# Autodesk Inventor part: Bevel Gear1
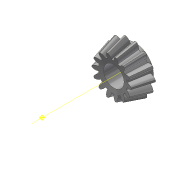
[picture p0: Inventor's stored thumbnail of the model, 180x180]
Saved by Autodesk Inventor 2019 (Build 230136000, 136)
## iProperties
Created: 2019-01
Part Number: Bevel Gear1
Material: Steel, Mild
Document SubType Name: Modeling
Designer: m.vorobev
Categories: <?xml version="1.0" encoding="UTF-16"?> <MemberInstance><Categories><FamilyTemplate><FamilyTemplateParameter ValueType="xs:double" Id="1" ObjectReferenceKey="da
Mass: 60.9118 g
Surface Area: 34.3074 cm^2
Volume: 7.7496 cm^3
Density: 7.86 g/cm^3
Appearance: Steel
CustomPartVersion: 1
Author: m.vorobev
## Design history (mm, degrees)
node "Top Point"
node "Mesh Plane2"
sketch "Teeth Body Sketch"
  geometry: L1 (0, 0)-(23.339, -115.145); L2 (23.339, -115.145)-(31.684, -113.095); L3 (31.684, -113.095)-(0, 0); L4 (28, -114)-(0, 0); L5 (18.368, -90.623)-(24.936, -89.009); L6 (23.339, -115.145)-(18.368, -90.623); L7 (31.684, -113.095)-(24.936, -89.009); L8 (0, -39.387)-(0, 6.564) reference; L9 (0, -114)-(31.684, -114)
  constraints: 16 end point, 4 point on line, 3 perpendicular, 2 collinear, 1 horizontal alignment, 1 vertical alignment
  dimensions: "d0" = 56 diameter of L4.start L8 (= da_de); "d1" = 46.67709 diameter of L1.end L8 (= da_dfe); "d2" = 63.3676 diameter of L2.end L8 (= da_dae); "d3" = 25 distance between parallel lines of L2 L5 (= da_b); "d4" = 113.09521 vertical distance of L2.end L1.start (= da_ve)
revolve "Teeth Body" sketch "Teeth Body Sketch" stored, may be unused: angle "d5" = 90 deg
node "Start Point"
node "Tooth Plane"
sketch "Start Sketch"
  geometry: L1 (0, -23.505)-(0, 10.645) reference; L2 (-1.996, -5.831)-(1.996, -5.831); A1 r 10.858 centre (-12.832, -5.13) between (-1.996, -5.831) and (-9.272, 5.128); A2 r 10.858 centre (12.832, -5.13) between (9.272, 5.128) and (1.996, -5.831); A3 r 35.203 centre (0, -28.832) between (9.272, 5.128) and (-9.272, 5.128); 1 further point
  constraints: 6 point on circle, 3 centre point, 3 symmetric about line, 2 end point, 1 coincident, 1 perpendicular, 1 other
  dimensions: "d7" = 10.85803 radius of A1 (= fd_rr); "d8" = 12.83159 horizontal distance of point (0, -28.832) A1.centre (= fd_x); "d9" = 23.7024 vertical distance of point (0, -28.832) A1.centre (= fd_y); "d57" = 35.20347 radius of A3 (= 0.5 x fd_dva + 0.3 x da_he); "d58" = 23.00101 distance from line of A3.centre L2 (= 0.5 x fd_dva - 1.12 x da_he)
node "End Point"
  node "End Plane"
sketch "3D Sketch Right"
  node "Helical Curve Right" dims "d65" = 419.42516 (computed from da_dm, da_delta, da_beta), "d66" = 31.5, "d67" = 56 (= da_de), "d68" = -2.40846 (= -da_delta), "d69" = 24.69567 (computed from fd_loft, da_delta)
node "End Plane Right"
sketch "End Sketch Right"
  geometry: L1 (0, -33.91)-(0, 15.115) reference; L2 (-1.566, -4.545)-(1.566, -4.545); A1 r 8.517 centre (-10.065, -3.995) between (-1.566, -4.545) and (-7.273, 4.051); A2 r 8.517 centre (10.065, -3.995) between (7.273, 4.051) and (1.566, -4.545); A3 r 27.613 centre (0, -22.586) between (7.273, 4.051) and (-7.273, 4.051); 1 further point
  constraints: 6 point on circle, 3 centre point, 3 symmetric about line, 2 end point, 1 coincident, 1 perpendicular, 1 other
  dimensions: "d70" = 10.06473 horizontal distance of A3.centre A1.centre (computed from fd_x, fd_ratio); "d71" = 18.59148 vertical distance of point (0, -22.586) A1.centre (computed from fd_y, fd_ratio); "d72" = 8.51673 radius of A1 (computed from fd_rr, fd_ratio); "d73" = 18.04133 distance from line of point (0, -22.586) L2 (computed from d58, fd_ratio); "d74" = 27.61259 radius of A3 (computed from d57, fd_ratio)
feature "Loft Right" sketch "End Sketch Right" dims "d75" = 0, "d77" = 0, "d79" = 0, "d80" = 90 deg, "d85" = 20, "d92" = 90 deg, "d93" = 90 deg, "da_teethtype" = 0 [user parameter]
pattern_circular "Circular Pattern Right" dims angle "d82" = 360 deg, "da_teethtype" = 0 [user parameter]
sketch "3D Sketch Left"
  node "Helical Curve Left" dims "d26" = 419.42516 (computed from da_dm, da_delta, da_beta), "d27" = 24.69567 (computed from fd_loft, da_delta), "d28" = 56 (= da_de), "d29" = -2.40846 (= -da_delta)
node "End Plane Left"
sketch "End Sketch Left" dims "d56" = 24.21699 (derived)
  geometry: L1 (0, -39.868)-(0, 21.084) reference; L2 (-1.566, -4.536)-(1.566, -4.536); A1 r 8.517 centre (-10.065, -3.986) between (-1.566, -4.536) and (-7.273, 4.06); A2 r 8.517 centre (10.065, -3.986) between (7.273, 4.06) and (1.566, -4.536); A3 r 27.613 centre (0, -22.577) between (7.273, 4.06) and (-7.273, 4.06); 2 further points; 1 other entity
  constraints: 6 point on circle, 3 centre point, 3 symmetric about line, 2 end point, 1 coincident, 2 other
  dimensions: "d30" = 8.51673 radius of A1 (computed from fd_rr, fd_ratio); "d31" = 10.06473 horizontal distance of point (0, -22.577) A1.centre (computed from fd_x, fd_ratio); "d32" = 18.59148 vertical distance of A1.centre point (0, -22.577) (computed from fd_y, fd_ratio); "d61" = 27.61259 radius of A3 (computed from d57, fd_ratio); "d62" = 18.04133 distance from line of point (0, -22.577) L2 (computed from d58, fd_ratio)
feature "Loft Left" sketch "End Sketch Left" dims "d35" = 0, "d37" = 0, "d39" = 0, "d40" = 90 deg, "d84" = 10, "d90" = 90 deg, "d91" = 90 deg, "da_teethtype" = 0 [user parameter]
pattern_circular "Circular Pattern Left" dims angle "d42" = 360 deg, "da_teethtype" = 0 [user parameter]
sketch "Body Sketch"
  geometry: L1 (0, -35.038)-(0, -19.531) reference; L2 (23.339, -115.145)-(18.368, -90.623) reference; L3 (18.368, -90.623)-(0, -90.623); L4 (23.339, -115.145)-(0, -115.145)
  constraints: 4 end point, 2 perpendicular, 2 point on line
revolve "Fix Body" sketch "Body Sketch" stored, may be unused: angle "d46" = 90 deg
sketch "Sketch6"
  geometry: L1 (28, -114)-(0, 0) reference; L2 (0, -37.8)-(0, 6.3) reference
feature "Pitch Diameter" sketch "Sketch6" dims angle "d47" = 90 deg
sketch "Sketch8"
  geometry: L1 (0, -119.009)-(-13, -119.009); L2 (-13, -119.009)-(-13, -91.941); L3 (-13, -91.941)-(0, -91.941); L4 (0, -91.941)-(0, -119.009); L5 (0, -91.941)-(-13, -91.941); L6 (-13, -91.941)-(-21.201, -89.927); L7 (-21.201, -89.927)-(0, -89.927); L8 (0, -89.927)-(0, -91.941); L9 (-18.368, -90.623)-(-24.936, -89.009) reference; L10 (0, -145.743)-(0, 24.291) reference; L11 (-23.339, -115.145)-(-23.111, -115.145) reference; L12 (-31.684, -113.095)-(-23.339, -115.145) reference; L13 (-23.339, -115.145)-(-13, -115.145); L14 (-13, -115.145)-(-13, -119.009); L15 (-13, -119.009)-(-23.339, -119.009); L16 (-23.339, -119.009)-(-23.339, -115.145); 1 further point
  constraints: 24 end point, 5 parallel, 3 horizontal, 2 collinear, 2 perpendicular
  dimensions: "d94" = 26 diameter of L2 L4; "d95" = 30 distance from line of L9.end L15
revolve "Revolution3" stored, may be unused: angle "d96" = 90 deg
revolve "Revolution4" stored, may be unused: angle "d97" = 90 deg
chamfer "Chamfer1" distance "d98" = 1; stored, may be unused: second distance "d99" = 2, angle "d100" = 45 deg
body "Solid1"
feature "Loft" dims "d17" = 0, "d18" = 90 deg, "d19" = 0, "d20" = 90 deg, "d89" = 0, "da_teethtype" = 0 [user parameter]
pattern_circular "Circular Pattern" dims angle "d22" = 360 deg, "d88" = 0, "da_teethtype" = 0 [user parameter]
sketch "End Sketch"
  geometry: L1 (0, -15.359)-(0, 6.983) reference; L2 (-1.566, -4.545)-(1.566, -4.545); A1 r 8.517 centre (-10.065, -3.995) between (-1.566, -4.545) and (-7.273, 4.051); A2 r 8.517 centre (10.065, -3.995) between (7.273, 4.051) and (1.566, -4.545); A3 r 27.613 centre (0, -22.586) between (7.273, 4.051) and (-7.273, 4.051); 1 further point
  constraints: 6 point on circle, 3 centre point, 3 symmetric about line, 2 end point, 1 coincident, 1 other
  dimensions: "d12" = 8.51673 radius of A1 (computed from fd_rr, fd_ratio); "d15" = 10.06473 horizontal distance of A1.centre point (0, -22.586) (computed from fd_x, fd_ratio); "d16" = 18.59148 vertical distance of A1.centre point (0, -22.586) (computed from fd_y, fd_ratio); "d59" = 27.61259 radius of A3 (computed from d57, fd_ratio); "d60" = 18.04133 distance from line of A3.centre L2 (computed from d58, fd_ratio)
body "Srf1"
other parameters: "da_b" = 25 [user parameter; used in 2 equation terms], "da_de" = 56 [user parameter; used in 4 equation terms], "da_dae" = 63.3676 [user parameter; used in 2 equation terms], "da_dfe" = 46.67709 [user parameter; used in 1 equation term], "da_le" = 117.38824 [user parameter; used in 1 equation term], "da_omega" = 90 deg [user parameter; used in 1 equation term], "da_beta" = 0 [user parameter; used in 2 equation terms], "da_delta" = 2.40846 [user parameter; used in 8 equation terms], "da_alpha" = 20 deg [user parameter; used in 2 equation terms], "da_he" = 8.59329 [user parameter; used in 4 equation terms], "da_ve" = 113.09521 [user parameter; used in 1 equation term], "fd_dv" = 57.6644 (computed from da_de, da_delta) [user parameter; used in 1 equation term], "fd_dva" = 65.25098 (computed from da_dae, da_delta) [user parameter; used in 3 equation terms], "fd_dvb" = 54.18681 (computed from fd_dv, da_alpha) [user parameter; used in 2 equation terms], "da_zv" = 144.161 [user parameter; used in 1 equation term], "fd_loft" = 25.42966 (= da_b + 0.05 x da_he) [user parameter; used in 4 equation terms], "fd_ratio" = 7.84371 (computed from da_le, fd_loft) [user parameter; used in 15 equation terms], "fd_rr" = 10.85803 (computed from fd_dd, fd_dvb) [user parameter; used in 6 equation terms], "fd_angle" = 1.10172 (computed from da_zv) [user parameter; used in 4 equation terms], "fd_x1" = 3.17008 (computed from da_dvw, fd_angle) [user parameter; used in 1 equation term], "fd_y1" = 28.6574 (computed from da_dvw, fd_angle) [user parameter; used in 1 equation term], "fd_x2" = 9.66151 (computed from fd_rr, fd_angle2, fd_angle) [user parameter; used in 1 equation term], "fd_y2" = 4.955 (computed from fd_rr, fd_angle2, fd_angle) [user parameter; used in 1 equation term], "fd_x" = 12.83159 (= fd_x1 + fd_x2) [user parameter; used in 4 equation terms], "fd_y" = 23.7024 (= fd_y1 - fd_y2) [user parameter; used in 4 equation terms], "fd_angle2" = 3.63711 (computed from fd_dvb, fd_dd, da_alpha) [user parameter; used in 2 equation terms], "fd_dd" = 58.37635 (= fd_dva - 0.8 x da_he) [user parameter; used in 2 equation terms], "da_dvw" = 57.6644 [user parameter; used in 2 equation terms], "d11" = 25.42966 (= fd_loft), "da_dm" = 50.03688 [user parameter; used in 2 equation terms], "da_x" = 0 [user parameter], "da_m" = 4 [user parameter], "d48" = 0, "d49" = 0, "d50" = 90 deg (= da_omega), "d51" = 2.24399 (computed from da_z), "d52" = 0, "d53" = 0, "d54" = 0
